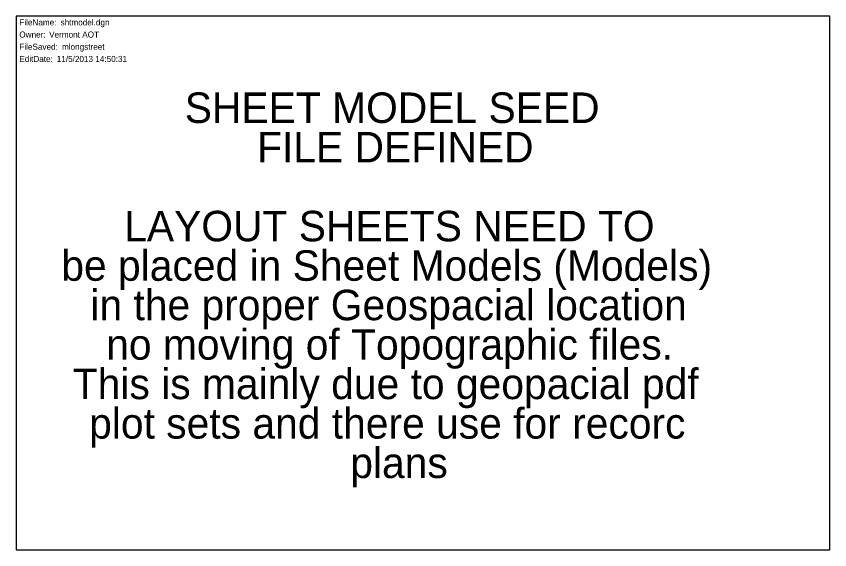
# Model space of a CAD drawing. Extents: x 0 to 2.67, y 0 to 1.75.
import ezdxf

# ---------------------------------------------------------------- set-up
doc = ezdxf.new("R2010")
doc.units = 0
doc.layers.add('Default', color=7, linetype='Continuous')

msp = doc.modelspace()

# ---------------------------------------------------------------- linework, layer by layer
at = {"layer": 'Default'}
msp.add_lwpolyline([(0, 0), (2.6667, 0), (2.6667, 1.75), (0, 1.75)], close=True, dxfattribs=at)

# ---------------------------------------------------------------- texts
for s, height, p in [('FileName: ', 0.02, (0.01, 1.72)), ('shtmodel.dgn', 0.02, (0.1451, 1.72)), ('Owner: ', 0.02, (0.01, 1.68)), ('Vermont AOT', 0.02, (0.1078, 1.68)), ('FileSaved: ', 0.02, (0.01, 1.64)), ('mlongstreet', 0.02, (0.1498, 1.64)), ('EditDate: ', 0.02, (0.01, 1.6)), ('11/5/2013 14:50:31', 0.02, (0.1327, 1.6)), ('SHEET MODEL SEED', 0.1, (0.5524, 1.4)), ('FILE DEFINED', 0.1, (0.7893, 1.2706)), ('LAYOUT SHEETS NEED TO', 0.1, (0.3538, 1.0117)), ('be placed in Sheet Models (Models)', 0.1, (0.1476, 0.8823)), ('in the proper Geospacial location', 0.1, (0.243, 0.7529)), ('no moving of Topographic files. ', 0.1, (0.2948, 0.6235)), ('This is mainly due to geopacial pdf', 0.1, (0.1853, 0.4941)), ('plot sets and there use for recorc', 0.1, (0.2389, 0.3646)), ('plans', 0.1, (1.0949, 0.2352))]:
    msp.add_text(s, height=height, dxfattribs=at).set_placement(p)

doc.saveas('drawing.dxf')
